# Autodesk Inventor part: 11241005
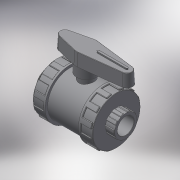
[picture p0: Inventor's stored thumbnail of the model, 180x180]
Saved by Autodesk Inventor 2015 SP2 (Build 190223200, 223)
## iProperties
Created: 2017-11
Part Number: 11241005
Material: Generic
Description: PLASSON BI STOP VALVE THR PVC 1/2"
Document SubType Name: Modeling
Designer: KIM
Density: 1 g/cm^3
Appearance: Default
Author: KIM
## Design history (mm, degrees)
derived "112410 - 112710.ipt"
feature "Solid1::112410 - 112710.ipt"
tag "TaggingFeature1"
body "Solid1"
other parameters: "d0" = 75, "d1" = 18.631, "d2" = 45, "d3" = 15, "d4" = 14.9048, "d5" = 10.5, "d7" = 26.0834, "d8" = 40.5, "d13" = 0.55893, "d23" = 15, "d24" = 43.2, "d25" = 0.37262, "d26" = 0.55893, "d27" = 6.75, "d28" = 3.375, "d29" = 11.25, "d30" = 0, "d35" = 0.55893, "d39" = 22.5, "d45" = 360 deg, "d47" = 0.37262, "d50" = 24.75, "d51" = 13.5, "d53" = 0, "d55" = 3.7262, "d56" = 1.8631, "d57" = 10.5, "d58" = 0, "d59" = 0.55893, "d61" = 360 deg, "d63" = 18, "d64" = 45, "d66" = 65, "d68" = 9, "d69" = 19.5, "d70" = 11.25, "d71" = 3 deg, "d73" = 0.9, "d74" = 26, "d75" = 1.35, "d76" = 0, "d77" = 0.37262, "G_" = 18.631, "l_" = 15, "H_" = 75, "K_" = 45, "F_" = 45, "J_" = 65, "d67" = 18, "d72" = 4.5
